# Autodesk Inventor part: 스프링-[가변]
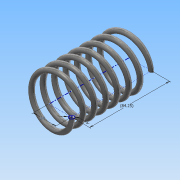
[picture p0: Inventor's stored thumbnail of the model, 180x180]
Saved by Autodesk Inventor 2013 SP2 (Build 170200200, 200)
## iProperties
Created: 2014-12
Part Number: 스프링-[가변]
Material: 강철, 탄소
Document SubType Name: Modeling
Designer: Administrator
Density: 7.87 g/cm^3
Mass: 161.108 g
Surface Area: 165.536 cm^2
Volume: 20.4712 cm^3
Author: Administrator
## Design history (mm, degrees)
sketch "스케치1"
  geometry: L1 (0, 0)-(24, 0); L2 (24, 0)-(24, 84.25); L3 (24, 84.25)-(0, 84.25); L4 (0, 84.25)-(0, 0); C1 r 2.5 at (24, 0)
  constraints: 8 end point, 2 parallel, 1 centre point, 1 coincident, 1 horizontal, 1 perpendicular
  dimensions: "d0" = 24 distance of L1.start L1.end; "d1" = 84.25 distance of L1.end L2.end (derived); "d2" = 5 diameter of C1
feature "코일1" pitch "d3" = 10; turns "d5" = 7; dims "d4" = 84.25 (= d1), "d6" = 0, angle "d7" = 90 deg, angle "d8" = 90 deg, "d9" = 0, "d10" = 0
sketch "스케치2"
  geometry: L1 (-26.5, 0)-(-21.5, 0) reference; 1 further point
  constraints: 1 horizontal alignment
extrude "돌출1" cut sketch "스케치2" distance "d11" = 10; taper "d12" = 0 deg
node "작업 평면1"
sketch "스케치3"
  geometry: L1 (5, 0)-(0, 0) reference; 1 further point
  constraints: 1 horizontal alignment
extrude "돌출2" cut sketch "스케치3" distance "d13" = 10; taper "d14" = 0 deg
node "솔리드1"
node "절단 모서리 투영1"
node "절단 모서리 투영2"
